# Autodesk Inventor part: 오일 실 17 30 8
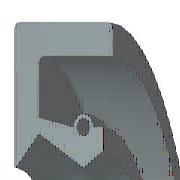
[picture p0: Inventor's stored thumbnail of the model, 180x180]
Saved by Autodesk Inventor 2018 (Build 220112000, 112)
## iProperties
Created: 2012-02
Part Number: 오일 실 17 30 8
Material: 고무
Description: 오일-실
Document SubType Name: Modeling
Standard: KS B 2804
Designer: mduedu
Standards Organization: KS
Language: ko-KR
Size Designation: D - 17 30 8
Categories: <MemberInstance><Categories><Category DisplayName="샤프트 부품" InternalName="7f7aeb1f-a693-4053-b835-cee3144e0d98" Mnemonic="SHFT"><Category DisplayName="실링" Intern
Density: 0.93 g/cm^3
Appearance: 고무 - 검은색 - 버전 1.1
Mass: 2.05499 g
Surface Area: 29.2219 cm^2
Volume: 2.20967 cm^3
IsCustomPart: 1
Author: mduedu
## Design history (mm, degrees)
revolve "본체" stored, may be unused: angle "d17" = 90 deg
revolve "스프링1" stored, may be unused: angle "d18" = 90 deg
fillet "모깎기3" dims "d43" = 0.5
body "Solid1"
sketch "스케치1"
  geometry: L1 (0, 15)-(8, 15); L2 (8, 13.25)-(1.75, 13.25); L3 (1.75, 10.25)-(4.9, 8.5); L4 (4.9, 8.5)-(0, 8.5); L5 (0, 0)-(9.586, 0) reference; L6 (4.9, 8.5)-(6.3, 9.375); L7 (0, 18)-(0, -3) reference; L8 (-1.941, 0)-(11.507, 0) reference; L9 (4.2, 10.6)-(1.75, 11.21); L10 (1.75, 11.21)-(1.75, 13.25); L11 (0, 15)-(0, 8.588); L12 (4.9, 8.5)-(0, 8.5); L13 (1.75, 10.25)-(0.152, 8.528); L14 (8, 15)-(8, 13.25); L15 (5.6, 10.6)-(6.3, 10.6); L16 (6.3, 10.6)-(6.3, 9.375); C1 r 0.455 at (4.9, 10.6); A1 r 0.7 centre (4.9, 10.6) between (5.6, 10.6) and (4.2, 10.6); A2 r 0.088 centre (0.088, 8.588) between (0, 8.588) and (0.152, 8.528); 1 further point
  constraints: 28 end point, 5 horizontal alignment, 5 point on line, 4 point on circle, 4 vertical alignment, 3 centre point, 3 tangent, 2 collinear, 2 horizontal, 2 perpendicular, 1 coincident, 1 parallel
  dimensions: "d0" = 30 diameter of L1 L5 (= SD2); "d1" = 1.75 distance of L1.end L2.start (= SD); "d2" = 0.91 diameter of C1 (= SPDI); "d3" = 1.4 diameter of A1 (= SPDA); "d4" = 17 diameter of L3.end L5 (= NND); "d5" = 20.5 diameter of L3.start L5 (= TKDM); "d7" = 22.42 diameter of L9.end L5 (= TKDM + 0.24 x SWDT); "d8" = 1.75 distance between parallel lines of L11 L10 (= SD); "d9" = 4.9 distance from line of L11 C1.centre (= SPDST); "d10" = 21.2 diameter of C1.centre L5 (= HLDM); "d11" = 0.0875 radius of A2 (= 0.25 x LAB); "d12" = 6.3 distance between parallel lines of L11 L16 (= SDI); "d13" = 18.75 diameter of L6.end L5 (= ABDM); "d14" = 8 distance from line of L11 L1.end (= SWDT)
fillet "모깎기1" dims "d6" = 0.3 (= RR)
other parameters: "SD2" = 30 [user parameter; used in 1 equation term], "SWDT" = 8 [user parameter; used in 2 equation terms], "RR" = 0.3 [user parameter; used in 1 equation term], "SD" = 1.75 [user parameter; used in 2 equation terms], "NND" = 17 [user parameter; used in 1 equation term], "SPDA" = 1.4 [user parameter; used in 1 equation term], "SPDI" = 0.91 [user parameter; used in 1 equation term], "TKDM" = 20.5 [user parameter; used in 2 equation terms], "HLDM" = 21.2 [user parameter; used in 1 equation term], "ABDM" = 18.75 [user parameter; used in 1 equation term], "SDI" = 6.3 [user parameter; used in 1 equation term], "SPDST" = 4.9 [user parameter; used in 1 equation term], "LAB" = 0.35 [user parameter; used in 1 equation term], "d15" = 0, "d16" = 0, "d19" = 0
